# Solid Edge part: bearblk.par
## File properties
Author: edge
Template: normal.par
Last saved by: edge
Revision: 62
Application: Solid Edge
Material: aluminum
File Size: 0
Number of Sheets: 0
Number of Objects: 0
非切断部品: False
文書内容のタイプ: 0
Accuracy: 0.99
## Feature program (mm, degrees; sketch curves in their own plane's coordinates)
sketch for "ExtrudedProtrusion_1" plane through (0, 0, 0) normal (0, -1, 0) x-axis (1, 0, 0)
  line (-115, 20) -> (115, 20)
  line (115, 20) -> (115, -5)
  line (115, -5) -> (-115, -5)
  line (-115, -5) -> (-115, 20)
  dimension (linear) = 115
extrude "ExtrudedProtrusion_1" add finite 120 symmetric
sketch for "ExtrudedProtrusion_2" plane through (0, 0, 0) normal (0, -1, 0) x-axis (1, 0, 0)
  line (-30.6418, 80.7115) -> (30.6418, 29.2885)
  arc centre (0, 55) radius 40 from (30.6418, 29.2885) to (-30.6418, 80.7115) cw
extrude "ExtrudedProtrusion_2" add finite 150 symmetric
sketch for "unnamed Protrusion 1" plane through (0, 0, 0) normal (0, -1, 0) x-axis (1, 0, 0)
  line (30.6418, 29.2885) -> (41.7114, 20)
  line (41.7114, 20) -> (8, 10)
  line (8, 10) -> (8, 29.2885)
  line (8, 29.2885) -> (30.6418, 29.2885)
extrude "unnamed Protrusion 1" add to key point symmetric
sketch for "ExtrudedProtrusion_4" plane through (4.8451, 0, 50.9344) normal (0.642788, 0, 0.766044) x-axis (0, 1, 0)
  line (-60, 28.3249) -> (-60, 71.3249)
  line (-60, 71.3249) -> (60, 71.3249)
  line (60, 71.3249) -> (60, 28.3249)
  line (60, 28.3249) -> (-60, 28.3249)
  dimension (linear) = 60
extrude "ExtrudedProtrusion_4" add finite 15 along -normal
fillet "Round_1" radius 10
fillet "Round_2" radius 6.5
fillet "Round_3" radius 13
fillet "Round_4" radius 8
sketch for "unnamed Hole 1" plane through (0, 0, 0) normal (0, -1, 0) x-axis (1, 0, 0)
  hole centre (0, 55) bore radius 25
hole "unnamed Hole 1" through
rib "Rib_1"  Thickness = 15.875 mm
sketch for "unnamed Hole 2" plane through (0, 0, 0) normal (0, 0, 1) x-axis (1, 0, 0)
  hole centre (-85, 40) bore radius 6
hole "unnamed Hole 2" through
sketch for "unnamed Hole 3" plane through (0, 0, 0) normal (0, 0, 1) x-axis (1, 0, 0)
  hole centre (-85, -30) bore radius 6
hole "unnamed Hole 3" through
sketch for "unnamed Hole 4" plane through (0, 0, 0) normal (0, 0, 1) x-axis (1, 0, 0)
  hole centre (85, -30) bore radius 6
hole "unnamed Hole 4" through
sketch for "unnamed Hole 5" plane through (0, 0, 0) normal (0, 0, 1) x-axis (1, 0, 0)
  hole centre (85, 40) bore radius 6
hole "unnamed Hole 5" through
sketch for "unnamed Hole 6" plane through (-34.3933, 0, 83.8594) normal (0.642788, 0, 0.766044) x-axis (0, 1, 0)
  hole centre (-35, 5.1027) bore radius 6
hole "unnamed Hole 6" through
sketch for "unnamed Hole 7" plane through (-34.3933, 0, 83.8594) normal (0.642788, 0, 0.766044) x-axis (0, 1, 0)
  hole centre (35, 5.1027) bore radius 6
hole "unnamed Hole 7" through
sketch for "unnamed Hole 8" plane through (29.1336, 0, 30.554) normal (0.642788, 0, 0.766044) x-axis (0, 1, 0)
  hole centre (-35, -1.9688) bore radius 6
hole "unnamed Hole 8" finite
sketch for "unnamed Hole 9" plane through (29.1336, 0, 30.554) normal (0.642788, 0, 0.766044) x-axis (0, 1, 0)
  hole centre (35, -1.9688) bore radius 6
hole "unnamed Hole 9" finite
holes "UserDefinedPattern_1": "unnamed Hole 2", "unnamed Hole 3", "unnamed Hole 4", "unnamed Hole 5"
holes "UserDefinedPattern_2": "unnamed Hole 6", "unnamed Hole 7"
holes "UserDefinedPattern_3": "unnamed Hole 8", "unnamed Hole 9"
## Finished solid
Body 1: solid body, 44 faces, 108 edges, 60 vertices.
  Faces by surface: plane 23, cylinder 19, torus 2
  Edges by curve: line 60, circle 46, intersection 2
Bounding box of the edges (mm; curved faces can reach further): 230.000 x 150.000 x 101.781, from (-115, -75, -5) to (115, 75, 96.7812).
Cylindrical faces by radius (mm): R6 x8, R6.5 x4, R10 x2, R13 x2, R25 x1, R40 x2
Toroidal faces (ring radius, tube radius in mm): R48 r8 x2
Planar faces by outward normal: +x 1, +y 4, +z 3, -x 1, -y 4, -z 1, oblique 9
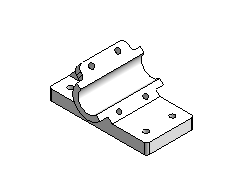
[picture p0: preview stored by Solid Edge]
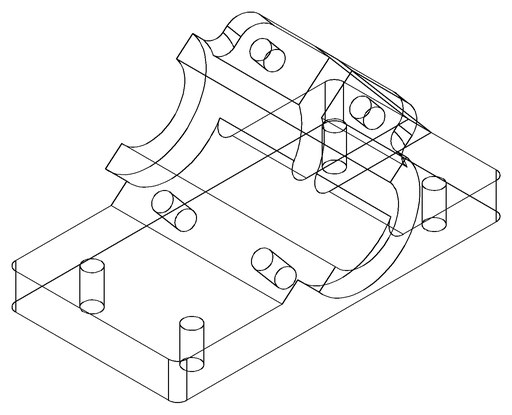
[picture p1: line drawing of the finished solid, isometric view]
